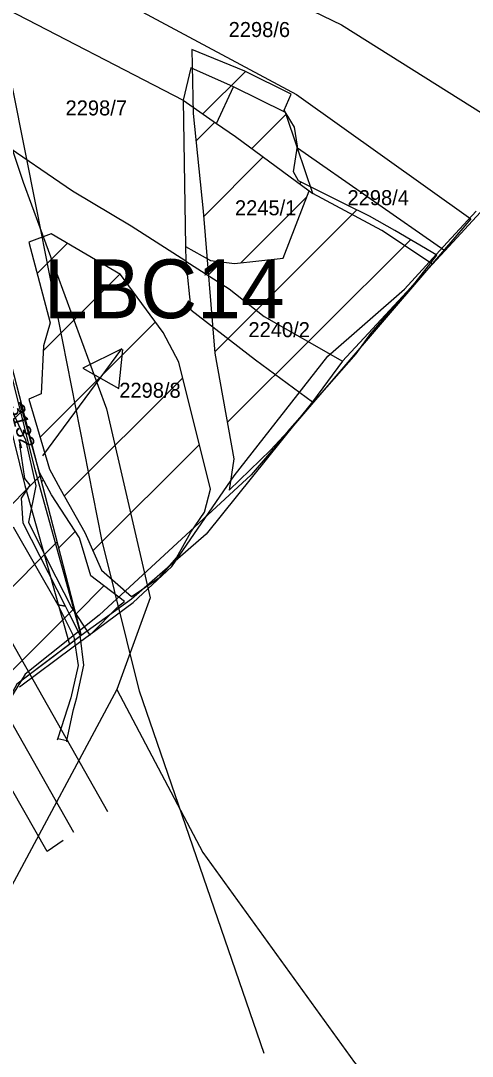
# Model space of a CAD drawing. Extents: x -564810 to -550519, y -1045831 to -1034011.
# Drawn here: x -551709.7 to -551556.4, y -1038400.2 to -1038048.4 of the extents above; entities that cross this region are included whole.
import ezdxf

# ---------------------------------------------------------------- set-up
doc = ezdxf.new("R2010")
doc.units = 0
for name, color, linetype in [('KN stav', 7, 'Continuous'), ('Lesní porost', 7, 'Continuous'), ('Obvod KPU', 7, 'Continuous'), ('Odvodněné plochy', 7, 'Continuous'), ('Parcelní čísla', 7, 'Continuous'), ('přeložka st silnice', 7, 'Continuous'), ('STG', 7, 'Continuous'), ('Vedení VN', 7, 'Continuous'), ('vodní toky', 7, 'Continuous'), ('Vrstva 18', 7, 'Continuous'), ('Vrstva 33', 7, 'Continuous'), ('Vrstva 4', 7, 'Continuous'), ('Vrstva 5', 7, 'Continuous')]:
    doc.layers.add(name, color=color, linetype=linetype)

msp = doc.modelspace()

# ---------------------------------------------------------------- linework, layer by layer
at = {"layer": 'KN stav'}
for p, q in [((-551728.56, -1038037.07), (-551654.51, -1038075.43)), ((-551631.33, -1038035.02), (-551600.73, -1038049.76)), ((-551600.73, -1038049.76), (-551530.18, -1038094.24)), ((-551651.94, -1038064.44), (-551654.51, -1038075.43)), ((-551637.38, -1038070.9), (-551651.94, -1038064.44)), ((-551619.73, -1038079.59), (-551637.38, -1038070.9)), ((-551692.11, -1038106.3), (-551739.41, -1038074.07)), ((-551654.51, -1038075.43), (-551653.72, -1038125.1)), ((-551615.66, -1038091.75), (-551619.73, -1038079.59)), ((-551565.72, -1038126.6), (-551615.66, -1038091.75)), ((-551610.54, -1038107.05), (-551615.66, -1038091.75)), ((-551672.18, -1038118.25), (-551692.11, -1038106.3)), ((-551587.07, -1038119.72), (-551610.54, -1038107.05)), ((-551552.15, -1038111.95), (-551565.72, -1038126.6)), ((-551653.64, -1038130.05), (-551672.18, -1038118.25)), ((-551569.87, -1038131.08), (-551587.07, -1038119.72)), ((-551653.72, -1038125.1), (-551653.64, -1038130.05)), ((-551565.72, -1038126.6), (-551569.87, -1038131.08)), ((-551653.64, -1038130.05), (-551651.92, -1038146.59)), ((-551653.64, -1038130.05), (-551638.88, -1038139.45)), ((-551569.87, -1038131.08), (-551600.42, -1038164.06)), ((-551638.88, -1038139.45), (-551627.03, -1038148.85)), ((-551651.92, -1038146.59), (-551629.99, -1038163.67)), ((-551627.03, -1038148.85), (-551600.42, -1038164.06)), ((-551704.91, -1038200.48), (-551715.43, -1038158.04)), ((-551719.41, -1038161.93), (-551708.25, -1038206.35)), ((-551629.99, -1038163.67), (-551610.66, -1038177.88)), ((-551600.42, -1038164.06), (-551610.66, -1038177.88)), ((-551610.66, -1038177.88), (-551646.74, -1038222.86)), ((-551689.18, -1038257.3), (-551704.91, -1038200.48)), ((-551708.25, -1038206.35), (-551693.15, -1038260.28)), ((-551646.74, -1038222.86), (-551672.12, -1038244.9)), ((-551672.12, -1038244.9), (-551689.18, -1038257.3)), ((-551689.18, -1038257.3), (-551693.15, -1038260.28)), ((-551693.15, -1038260.28), (-551710.98, -1038273.85))]:
    msp.add_line(p, q, dxfattribs=at)
at = {"layer": 'Lesní porost'}
for p, q in [((-551633.56, -1038065.49), (-551651.61, -1038058.14)), ((-551651.61, -1038058.14), (-551651.08, -1038079.92)), ((-551647.81, -1038080.08), (-551633.33, -1038065.6)), ((-551617.8, -1038073.4), (-551633.56, -1038065.49)), ((-551620.27, -1038078.75), (-551617.8, -1038073.4)), ((-551651.08, -1038079.92), (-551647.69, -1038113.07)), ((-551631.25, -1038091.8), (-551619.47, -1038080.03)), ((-551617.95, -1038082.48), (-551620.27, -1038078.75)), ((-551650.13, -1038089.21), (-551643.79, -1038082.87)), ((-551616.77, -1038084.56), (-551617.95, -1038082.48)), ((-551615.75, -1038091.01), (-551616.77, -1038084.56)), ((-551617.02, -1038099.69), (-551615.75, -1038091.01)), ((-551647.54, -1038114.9), (-551627.33, -1038094.69)), ((-551615.33, -1038102.84), (-551617.02, -1038099.69)), ((-551599.51, -1038110.73), (-551615.33, -1038102.84)), ((-551614.96, -1038103.79), (-551614.44, -1038103.28)), ((-551634.99, -1038130.63), (-551612.56, -1038108.21)), ((-551591.24, -1038114.85), (-551599.51, -1038110.73)), ((-551647.69, -1038113.07), (-551643.75, -1038161.3)), ((-551643.78, -1038160.91), (-551595.57, -1038112.69)), ((-551582.7, -1038119.68), (-551591.24, -1038114.85)), ((-551699.32, -1038120.77), (-551706.95, -1038123.66)), ((-551675.85, -1038134.58), (-551699.32, -1038120.77)), ((-551639.53, -1038184.94), (-551577.38, -1038122.79)), ((-551568.44, -1038128.03), (-551582.7, -1038119.68)), ((-551706.95, -1038123.66), (-551699.68, -1038151.07)), ((-551704.13, -1038134.31), (-551693.82, -1038124.01)), ((-551575.75, -1038137.47), (-551568.44, -1038128.03)), ((-551645.92, -1038134.76), (-551641.49, -1038130.32)), ((-551702.07, -1038160.54), (-551676.01, -1038134.48)), ((-551661.28, -1038154.28), (-551675.85, -1038134.58)), ((-551590.84, -1038154.71), (-551575.75, -1038137.47)), ((-551699.68, -1038151.07), (-551701.99, -1038158.88)), ((-551681.59, -1038168.34), (-551663.94, -1038150.69)), ((-551655.94, -1038164.45), (-551661.28, -1038154.28)), ((-551595.79, -1038161.56), (-551590.84, -1038154.71)), ((-551701.99, -1038158.88), (-551702.76, -1038175.11)), ((-551643.75, -1038161.3), (-551637.33, -1038197.25)), ((-551618.99, -1038187.98), (-551595.79, -1038161.56)), ((-551645.23, -1038207.54), (-551655.94, -1038164.45)), ((-551703.1, -1038189.86), (-551682.93, -1038169.68)), ((-551694.88, -1038209.92), (-551654.64, -1038169.68)), ((-551702.76, -1038175.11), (-551706.89, -1038176.97)), ((-551713.44, -1038179.14), (-551708.07, -1038190.75)), ((-551703.26, -1038201.93), (-551709.99, -1038178)), ((-551706.89, -1038176.97), (-551699.9, -1038200.75)), ((-551624.89, -1038194.36), (-551618.99, -1038187.98)), ((-551708.07, -1038190.75), (-551704.5, -1038206.38)), ((-551685.17, -1038228.49), (-551649.01, -1038192.33)), ((-551638.86, -1038207.88), (-551624.89, -1038194.36)), ((-551637.33, -1038197.25), (-551638.86, -1038207.88)), ((-551699.25, -1038209.48), (-551703.26, -1038201.93)), ((-551699.9, -1038200.75), (-551696.29, -1038207.4)), ((-551702.67, -1038205.12), (-551701.95, -1038204.39)), ((-551689.77, -1038224.1), (-551699.25, -1038209.48)), ((-551696.29, -1038207.4), (-551687.95, -1038222.26)), ((-551647.33, -1038215.35), (-551645.23, -1038207.54)), ((-551651.92, -1038222.22), (-551647.33, -1038215.35)), ((-551696.86, -1038227.59), (-551691.19, -1038221.91)), ((-551685.86, -1038237.03), (-551689.77, -1038224.1)), ((-551687.95, -1038222.26), (-551682.25, -1038235.04)), ((-551656.83, -1038230.85), (-551651.92, -1038222.22)), ((-551662.47, -1038237.42), (-551656.83, -1038230.85)), ((-551700.37, -1038232.21), (-551692.48, -1038247.72)), ((-551682.25, -1038235.04), (-551672.08, -1038244.06)), ((-551674.45, -1038245.77), (-551685.86, -1038237.03)), ((-551670.15, -1038242.8), (-551662.47, -1038237.42)), ((-551690.98, -1038249.99), (-551681.42, -1038240.43)), ((-551676.44, -1038247.27), (-551674.45, -1038245.77)), ((-551672.08, -1038244.06), (-551670.15, -1038242.8)), ((-551686.24, -1038257.15), (-551676.44, -1038247.27))]:
    msp.add_line(p, q, dxfattribs=at)
for points in [[(-551704.5, -1038206.38), (-551707.06, -1038218.76), (-551700.37, -1038232.21)], [(-551692.48, -1038247.72), (-551686.24, -1038257.15)]]:
    msp.add_lwpolyline(points, dxfattribs=at)
at = {"layer": 'Obvod KPU'}
for p, q in [((-551564.9, -1038123.8), (-551555.05, -1038113.06)), ((-551579.38, -1038139.6), (-551564.9, -1038123.8)), ((-551605.43, -1038162.35), (-551579.38, -1038139.6)), ((-551637.23, -1038203.05), (-551605.43, -1038162.35)), ((-551641.97, -1038209.96), (-551637.23, -1038203.05)), ((-551658.35, -1038233.81), (-551641.97, -1038209.96)), ((-551671.54, -1038246.08), (-551658.35, -1038233.81)), ((-551686.31, -1038257.06), (-551671.54, -1038246.08)), ((-551691.88, -1038261.18), (-551686.31, -1038257.06)), ((-551710.12, -1038274.76), (-551691.88, -1038261.18))]:
    msp.add_line(p, q, dxfattribs=at)
at = {"layer": 'Odvodněné plochy'}
msp.add_lwpolyline([(-551900.29, -1037774.7), (-551876.37, -1037829.93), (-551708.89, -1037960.63), (-551690.1, -1037909.35), (-551669.82, -1037879.93), (-551694.74, -1037844.42), (-551698.65, -1037808.41), (-551689.26, -1037784.27), (-551667.21, -1037804.56), (-551640.8, -1037888.84), (-551647.32, -1037914.08), (-551658.81, -1037951.1), (-551629.83, -1037965.01), (-551727.19, -1038035.65), (-551741.1, -1038056.52), (-551689.18, -1038257.3), (-551710.98, -1038273.85), (-551737.72, -1038322.56), (-551754.67, -1038342.59), (-551787.84, -1038361.97), (-551812.91, -1038372.05), (-551836.77, -1038387.52), (-551852.44, -1038396.9), (-551895.44, -1038426.86)], dxfattribs=at)
at = {"layer": 'přeložka st silnice'}
for p, q in [((-552156.96, -1038628.64), (-551709, -1038180.67)), ((-552136.29, -1038636.25), (-551703.18, -1038203.14)), ((-551935.4, -1038463.65), (-551697.37, -1038225.62)), ((-551820.35, -1038376.88), (-551691.56, -1038248.09))]:
    msp.add_line(p, q, dxfattribs=at)
at = {"layer": 'STG'}
msp.add_lwpolyline([(-551627.07, -1038399.26), (-551669.32, -1038276.14), (-551682.18, -1038224.68), (-551704.23, -1038112.59), (-551720.76, -1038029.9), (-551711.57, -1037982.12), (-551685.86, -1037877.38), (-551654.62, -1037765.29), (-551641.76, -1037690.13)], dxfattribs=at)
at = {"layer": 'Vedení VN'}
for points in [[(-552432.62, -1036280.68), (-552381.75, -1036354.88), (-552340.78, -1036472.89), (-552289.91, -1036771.81), (-551953.63, -1037825.94), (-551890.75, -1037944.66), (-551680.22, -1038317.07)], [(-551695.24, -1038326.94), (-551700.71, -1038330.65), (-551972.06, -1037853.73), (-552325.94, -1036770.4), (-552370.45, -1036480.66), (-552411.81, -1036369.59), (-552471.47, -1036287.75)], [(-551691.6, -1038324.25), (-551753.32, -1038215.22), (-551815.56, -1038104.9), (-551888.03, -1037977.11), (-551957.29, -1037854.44), (-552010.26, -1037691.39), (-552038.99, -1037602.42), (-552068.06, -1037512.55)]]:
    msp.add_lwpolyline(points, dxfattribs=at)
at = {"layer": 'vodní toky'}
for p, q in [((-551708.31, -1038203.88), (-551710.03, -1038192.37)), ((-551709.37, -1038210.65), (-551706.44, -1038206.16)), ((-551706.44, -1038206.16), (-551708.31, -1038203.88)), ((-551708.8, -1038219.06), (-551709.37, -1038210.65)), ((-551712.25, -1038220.31), (-551697.1, -1038246.87)), ((-551694.47, -1038247.35), (-551708.8, -1038219.06)), ((-551697.1, -1038246.87), (-551694.47, -1038247.35)), ((-551697.1, -1038246.87), (-551693.6, -1038253.83)), ((-551689.51, -1038257.18), (-551693.1, -1038250.06)), ((-551693.6, -1038253.83), (-551691.69, -1038257.7)), ((-551691.69, -1038257.7), (-551690.17, -1038267.42)), ((-551688.26, -1038267.41), (-551689.51, -1038257.18)), ((-551690.17, -1038267.42), (-551692.62, -1038278.46)), ((-551690.61, -1038278.29), (-551688.26, -1038267.41)), ((-551692.62, -1038278.46), (-551697.08, -1038292.18)), ((-551691.79, -1038282.38), (-551690.61, -1038278.29)), ((-551693.98, -1038292.93), (-551691.79, -1038282.38)), ((-551697.08, -1038292.18), (-551697.35, -1038292.87)), ((-551697.08, -1038292.18), (-551697.11, -1038292.25)), ((-551697.11, -1038292.25), (-551693.99, -1038292.99)), ((-551693.98, -1038292.93), (-551694.1, -1038293.42)), ((-551693.99, -1038292.99), (-551693.98, -1038292.93))]:
    msp.add_line(p, q, dxfattribs=at)
for points in [[(-551702.14, -1038196.2), (-551675.37, -1038159.91), (-551688.63, -1038166.5), (-551676.37, -1038173.34), (-551675.04, -1038160.16)], [(-551693.1, -1038250.06), (-551694.47, -1038247.35), (-551697.1, -1038246.87)]]:
    msp.add_lwpolyline(points, dxfattribs=at)
at = {"layer": 'Vrstva 18'}
msp.add_lwpolyline([(-551741.42, -1038323.75), (-551751.22, -1038244.87), (-551757.62, -1038211.19), (-551758.47, -1038152.78), (-551773.39, -1038093.09), (-551757.19, -1038071.77), (-551746.11, -1038049.17), (-551730.33, -1038024.44), (-551727.35, -1038013.79), (-551616.07, -1038073.48), (-551556.8, -1038115.69), (-551631.42, -1038202.66), (-551683, -1038250.42), (-551708.16, -1038270.45), (-551740.14, -1038322.47)], dxfattribs=at)
at = {"layer": 'Vrstva 33'}
for points in [[(-552013.57, -1038243.96), (-551932.89, -1038182.35), (-551873.21, -1038135.72), (-551811.42, -1038083.43), (-551762.51, -1038047.4), (-551730.02, -1038007.12), (-551730.02, -1038039.63), (-551708.84, -1038103.22), (-551680.59, -1038180.23), (-551665.76, -1038244.53), (-551677.06, -1038275.61), (-551714.49, -1038345.56), (-551787.23, -1038465.89), (-551749.09, -1038546.43)], [(-551677.06, -1038275.61), (-551647.89, -1038331.03), (-551596.34, -1038402.39), (-551527.84, -1038483.65), (-551460.04, -1038576.91), (-551396.48, -1038656.75), (-551353.4, -1038696.67), (-551332.21, -1038765.91), (-551313.85, -1038803.36), (-551287.01, -1038898.04), (-551220.63, -1039120.18), (-551086.44, -1039132.19)]]:
    msp.add_lwpolyline(points, dxfattribs=at)
at = {"layer": 'Vrstva 4'}
for p, q in [((-551643.19, -1038083.28), (-551637.38, -1038070.9)), ((-551654.51, -1038075.43), (-551643.19, -1038083.28)), ((-551643.19, -1038083.28), (-551636.71, -1038087.78)), ((-551636.71, -1038087.78), (-551611.77, -1038106.14)), ((-551620.6, -1038129.1), (-551611.77, -1038106.14)), ((-551611.77, -1038106.14), (-551610.54, -1038107.05)), ((-551653.72, -1038125.1), (-551645.2, -1038129.88)), ((-551645.2, -1038129.88), (-551637.09, -1038130.86)), ((-551637.09, -1038130.86), (-551620.6, -1038129.1))]:
    msp.add_line(p, q, dxfattribs=at)

# ---------------------------------------------------------------- texts
at = {"layer": 'Parcelní čísla'}
for s, p in [('2298/6', (-551639.08, -1038053.94)), ('2298/7', (-551694.46, -1038080.57)), ('2298/4', (-551598.72, -1038111.07)), ('2245/1', (-551636.93, -1038114.51)), ('2240/2', (-551632.35, -1038155.91)), ('2298/8', (-551676.21, -1038176.5))]:
    msp.add_text(s, height=5.1, dxfattribs=at).set_placement(p)
msp.add_text('3132', height=5.1, rotation=285.2897, dxfattribs=at).set_placement((-551713.62, -1038179.4))
at = {"layer": 'Vrstva 5'}
msp.add_text('LBC14', height=20, dxfattribs=at).set_placement((-551701.81, -1038149.48))

doc.saveas('drawing.dxf')
